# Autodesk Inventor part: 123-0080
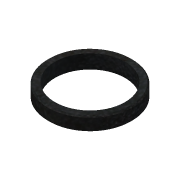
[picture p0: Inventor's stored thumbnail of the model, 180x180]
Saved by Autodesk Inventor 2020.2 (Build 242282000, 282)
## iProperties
Created: 2006-02
Part Number: 123-0080
Document SubType Name: Modeling
Designer: F.Stasiak
Description: Tuleja dystansowa 25x30x5
Material: St 5
Project: Przekładnia X51
Density: 7.85 g/cm^3
Appearance: Stal metaliczna (platerowana)
Manager: www.cadconsulting.pl
Company: Fabian Stasiak CAD Consulting
Author: F.Stasiak
Subject: Zbiór ćwiczeń. Autodesk Inventor 2020. Kurs podstawowy
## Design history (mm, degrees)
sketch "Szkic1"
  geometry: C1 r 12.5 at (0, 0); C2 r 15 at (0, 0); 1 further point
  constraints: 2 centre point, 2 coincident
  dimensions: "d0" = 25 diameter of C1; "d1" = 30 diameter of C2
extrude "Wyciągnięcie proste1" new body sketch "Szkic1" distance "d2" = 5; taper "d3" = 0 deg
chamfer "Faza1" distance "d4" = 0.5; stored, may be unused: second distance "d5" = 2, angle "d6" = 45 deg
node "Bryła1"
node "Korpusy bryłowe"
node "Korpusy powierzchniowe"
